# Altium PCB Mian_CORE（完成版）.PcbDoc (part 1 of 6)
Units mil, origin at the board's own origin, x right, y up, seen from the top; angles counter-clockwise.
Board outline 2755.91 x 1771.65 mil, 4 copper layers (TOP, GND02, PWR03, BOTTOM); 61 components, 130 nets, 4907 pads, 497 vias.
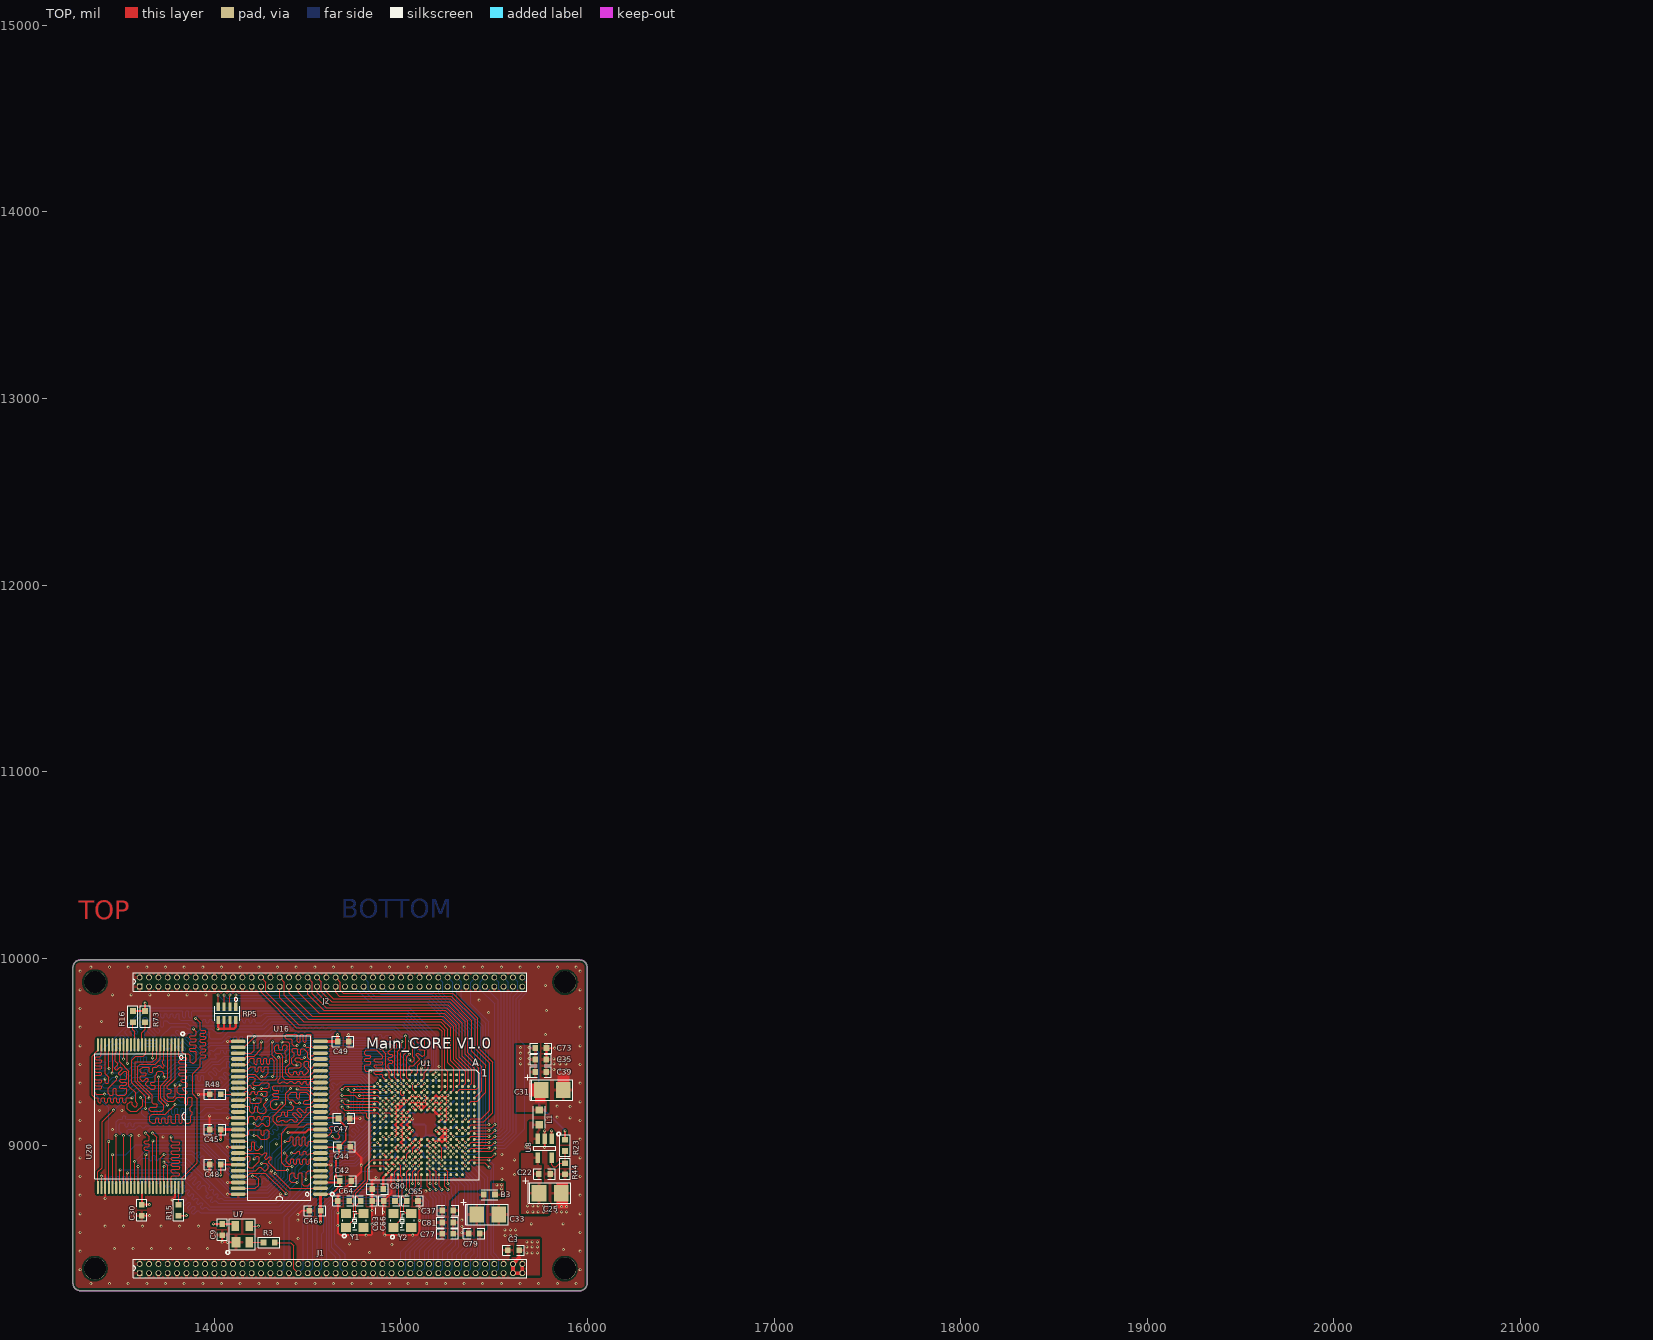
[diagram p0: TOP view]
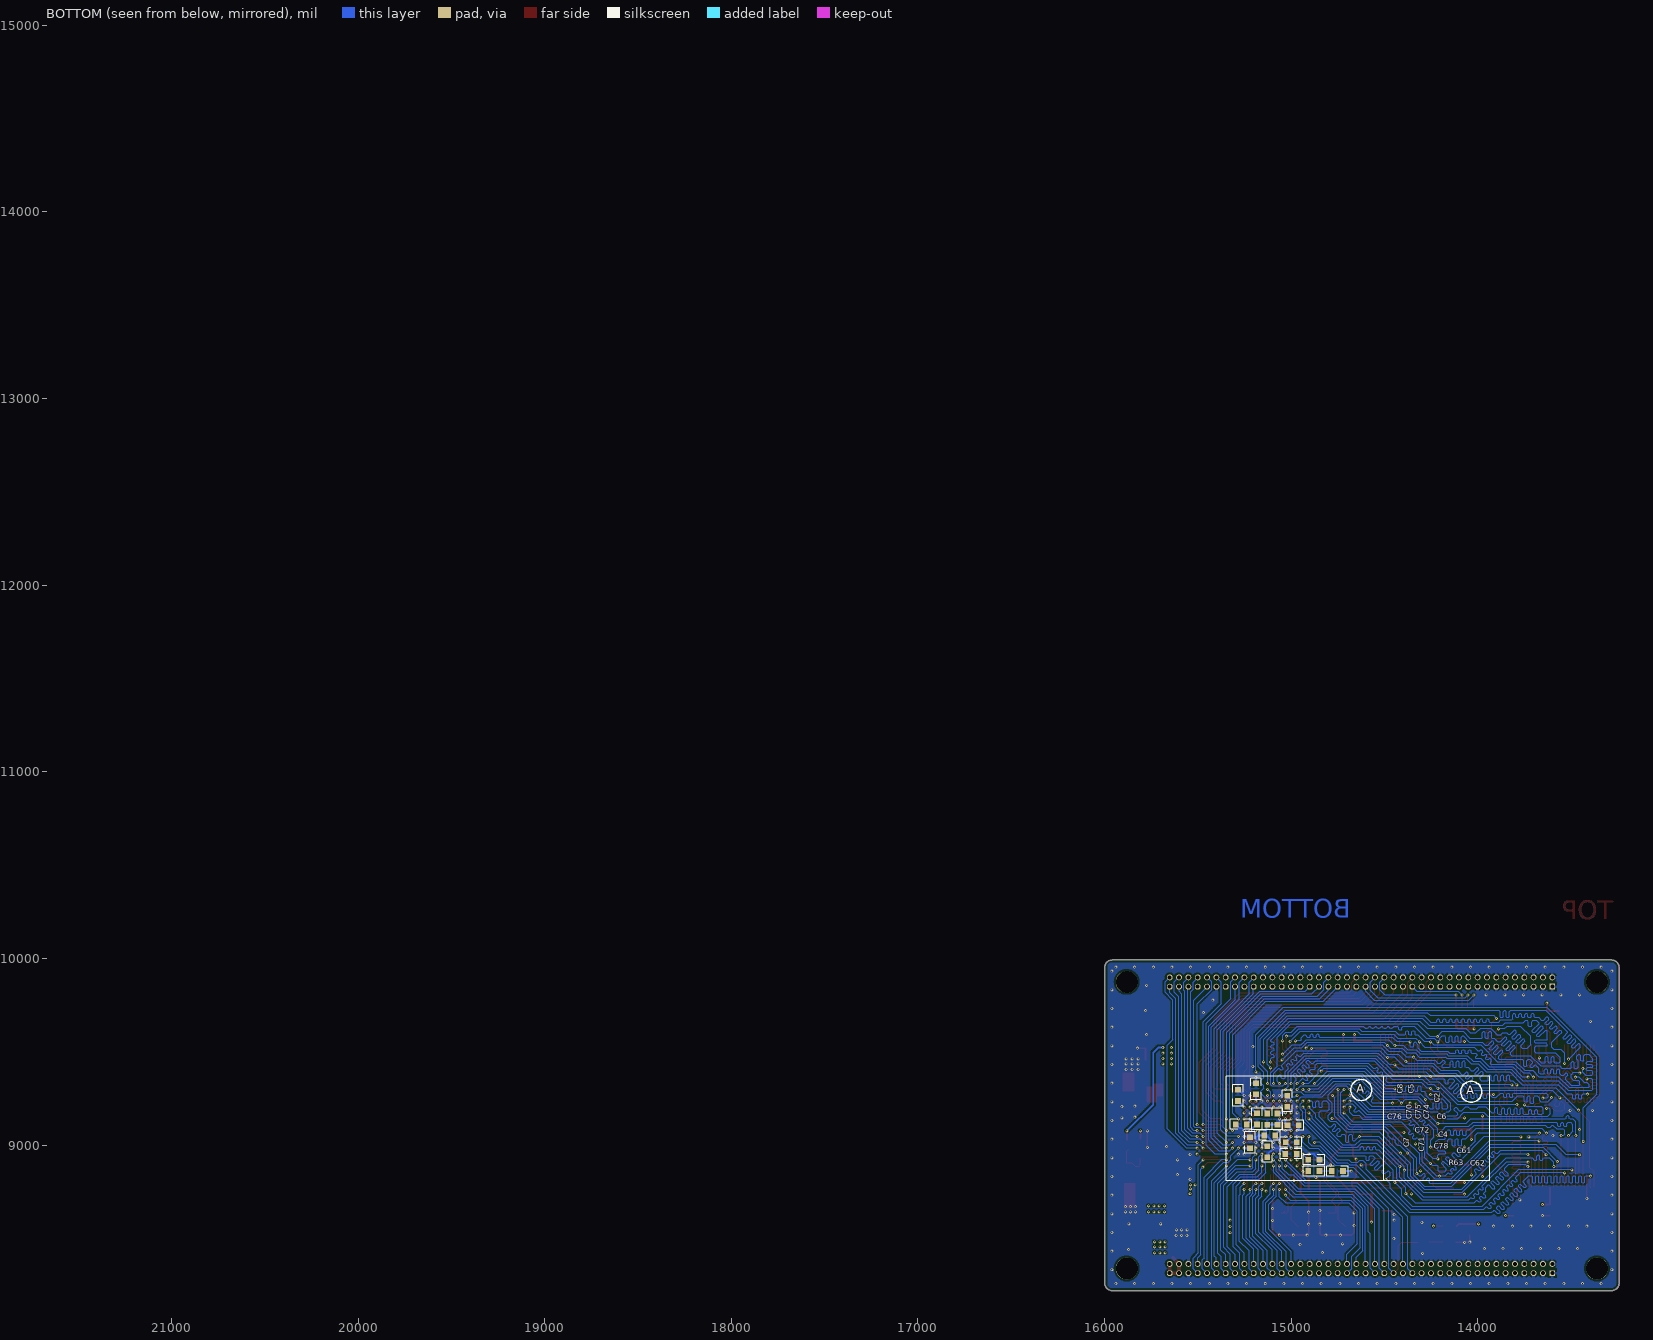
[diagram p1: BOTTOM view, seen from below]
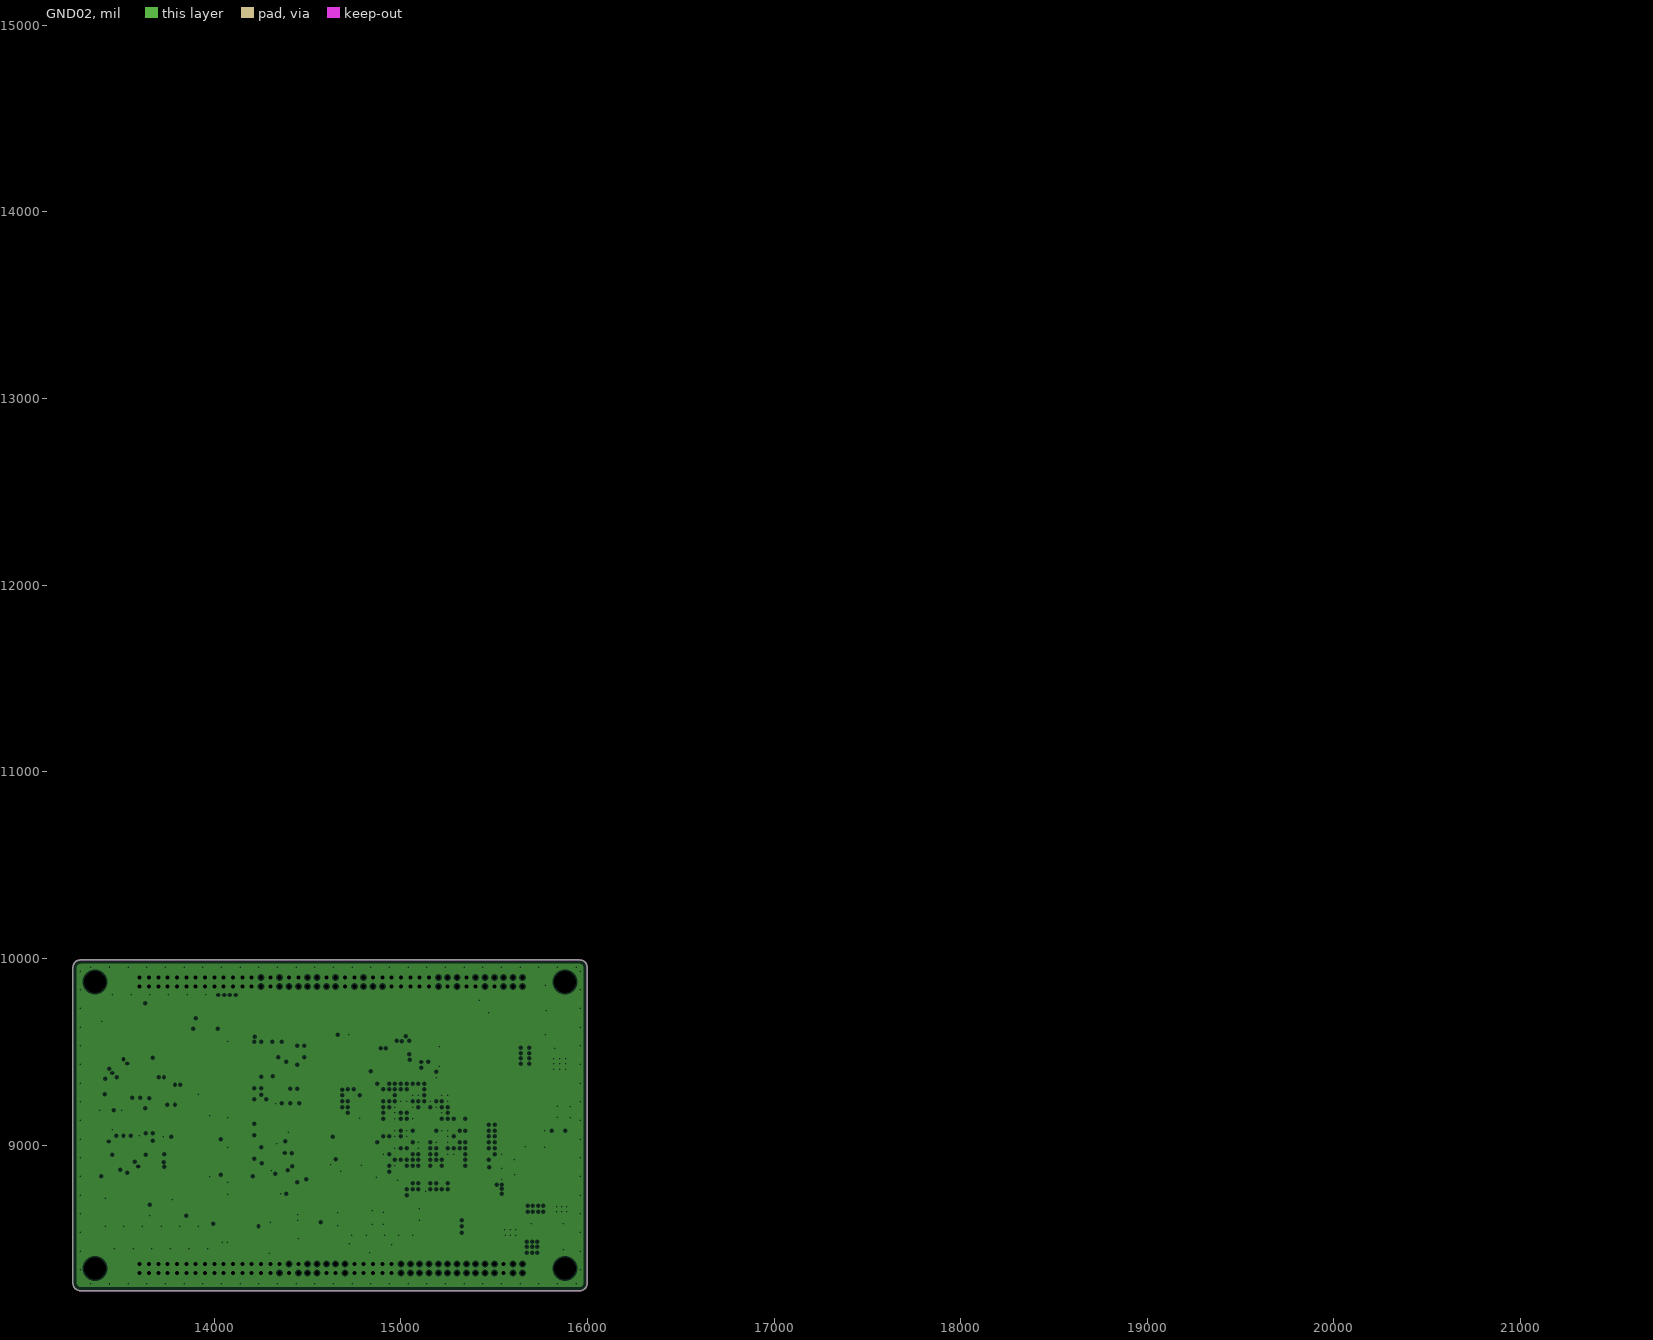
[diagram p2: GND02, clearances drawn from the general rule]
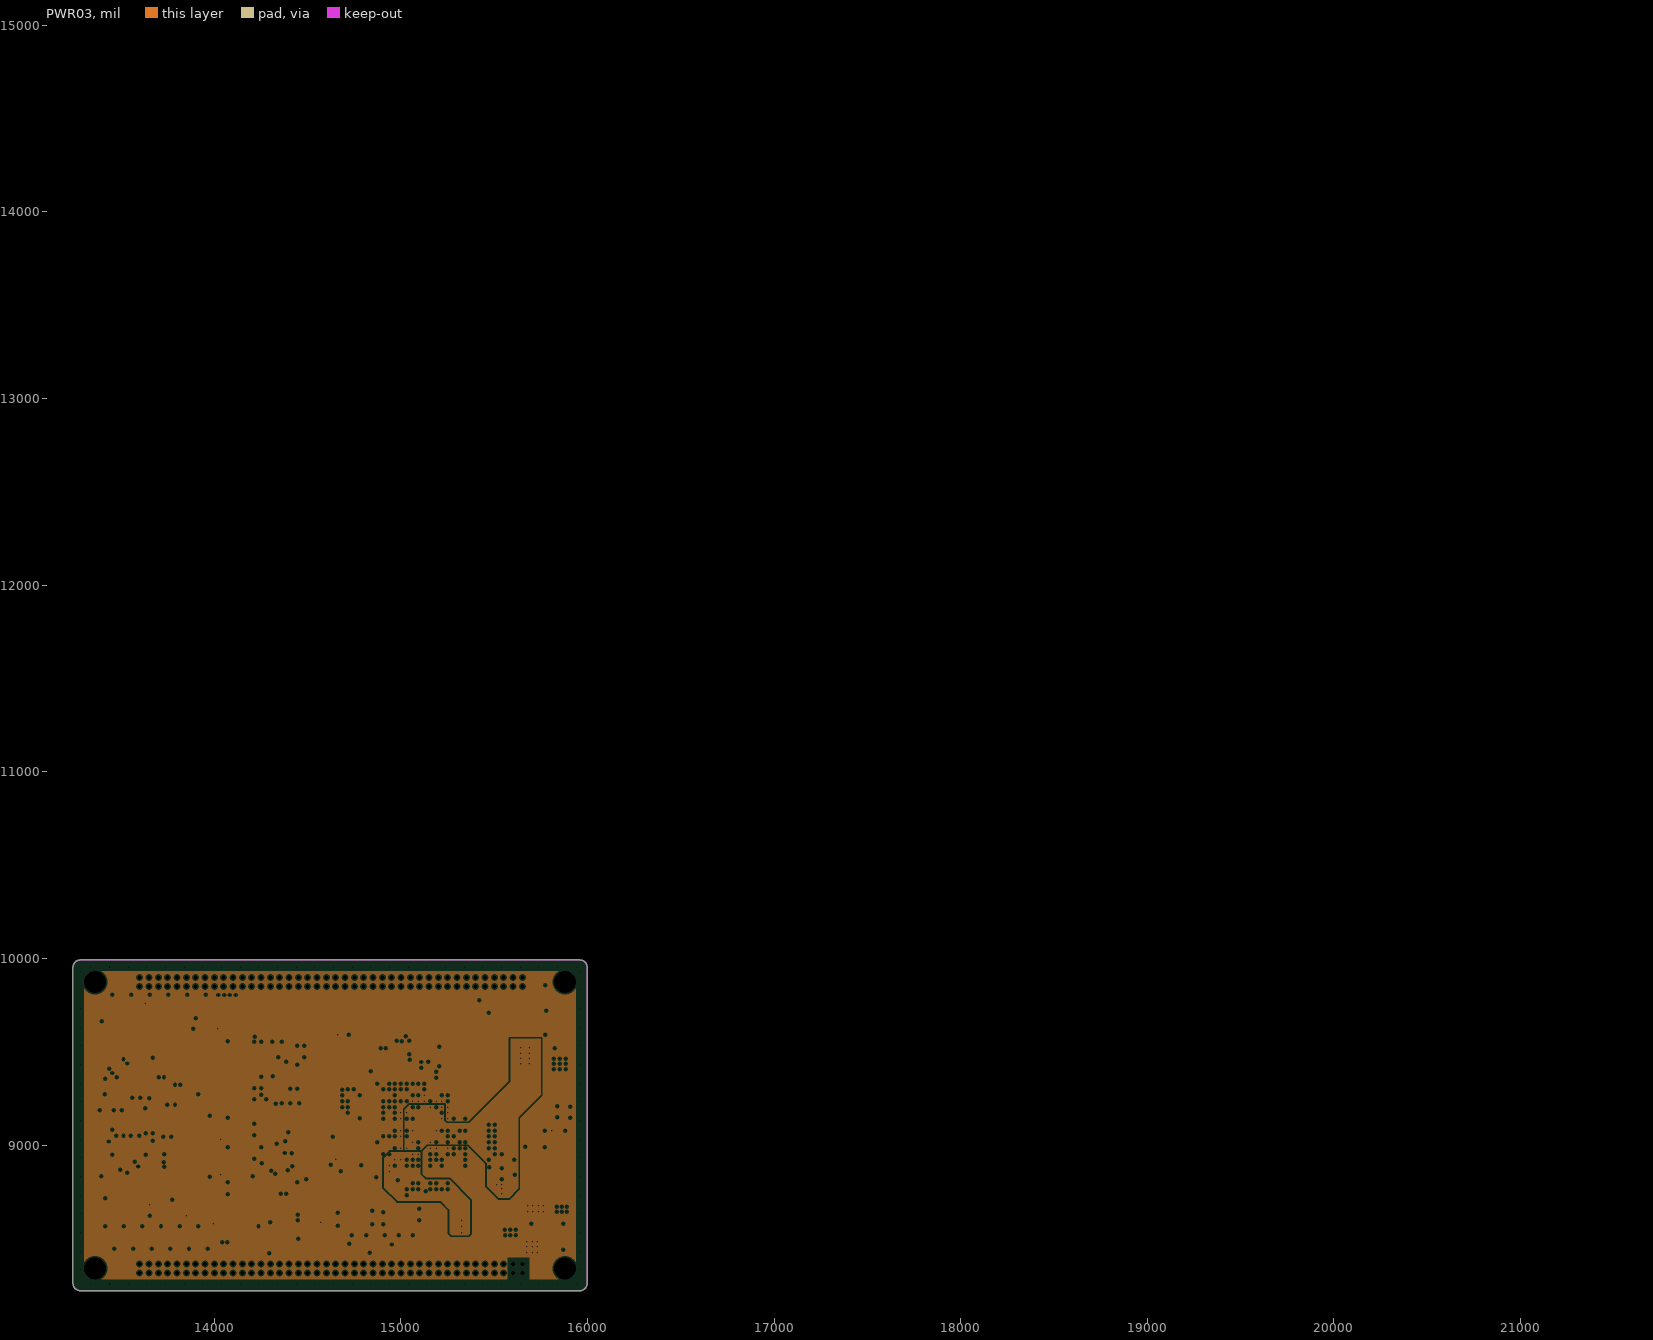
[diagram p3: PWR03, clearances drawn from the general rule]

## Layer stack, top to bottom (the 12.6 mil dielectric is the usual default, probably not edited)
TOP: signal copper 1.4
Dielectric: core 12.6, FR-4, Dk 4.8
GND02: plane copper 1.4, net GND
Dielectric: prepreg 12.6, FR-4, Dk 4.8
PWR03: plane copper 1.4, net (Multiple Nets)
Dielectric: core 12.6, FR-4, Dk 4.8
BOTTOM: signal copper 1.4

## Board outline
13243,8259.37 ccw(c13282.37,8259.37) 13282.37,8220 15959.54,8220 ccw(c15959.54,8259.37) 15998.91,8259.37 15998.91,9952.28 ccw(c15959.54,9952.28) 15959.54,9991.65 13282.37,9991.65 ccw(c13282.37,9952.28) 13243,9952.28

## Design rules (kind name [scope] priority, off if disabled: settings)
Clearance VIA-PLOY [(IsVia) vs INPOLY] p1: gap=5
Clearance POLY [(INPolygon)] p2: gap=10
Clearance ALL [All] p3: gap=4.5
PlaneClearance [All] p1: clearance=8
PlaneConnect [All] p1: planeconnectstyle=Relief reliefexpansion=6 reliefentries=4 reliefconductorwidth=10 reliefairgap=8
PolygonConnect PolygonConnect_via [isvia] p1: connectstyle=Direct reliefconductorwidth=10 reliefentries=4 polygonreliefangle="90 Angle"
PolygonConnect [All] p2: connectstyle=Relief reliefconductorwidth=15 reliefentries=4 polygonreliefangle="90 Angle"
RoutingVias [All] p1: holewidth=8 width=16 viastyle="Through Hole" minholewidth=8 minwidth=16 maxholewidth=8 maxwidth=16
SilkscreenOverComponentPads [All] p1: minsilkscreentomaskgap=10
SolderMaskExpansion [All] p1: expansion=2.5
Width PWR [InNetClass('PWR')] p1: maxlimit=60 minlimit=10 preferedwidth=12
Width [All] p2: maxlimit=5.5 minlimit=5.5 preferedwidth=5.5
25 further rules are at their usual default settings.

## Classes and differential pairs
net class ADD: A15 A16 A17 A18 A19 NCS0 NOE
net class adress: A0 A1 A2 A3 A4 A5 A6 A7 A8 A9 A10 A11 A12 A13 A14 LDQM0 LDQM1 LNSDCAS LNSDCS0 LNSDRAS NWE SDR_CKE0 SDR_CLK
net class D[0..31]: D0 D1 D2 D3 D4 D5 D6 D7 D8 D9 D10 D11 D12 D13 D14 D15
component class sdram: C42 C44 C45 C46 C47 C48 C49 R48 U16
component class EMC: U1
component class power: C2 C3 C4 C5 C6 C7 C8 C61 C62 C70 C71 C72 C73 C74 C75 C76 C77 C78 C79 C80 C81 R63
component class flash: C30 C63 C64 C65 C66 R15 R16 R73 U20 Y1 Y2
component class interface: B3 C9 C22 C25 C31 C33 C35 C37 C39 J1 J2 L1 R3 R23 R44 U7 U8
component class CPU: RP5
net class PWR: DP1V2 DP1V2_PLL DP3V3 GND
net class DZ: EXT_RST GPI_00 GPI_02 GPI_03 GPI_04 GPI_05 GPI_07 GPI_08 GPI_16 GPI_22 GPIO_00 GPIO_01 GPO_00 GPO_01 GPO_02 GPO_03 GPO_05 GPO_06 GPO_07 GPO_08 GPO_09 GPO_10 GPO_12 GPO_13 GPO_14 GPO_15 GPO_16 GPO_20 MISO0 MISO1 MOSI0 MOSI1 NCS1 NCS2 NRESET NSYSRESET NTRST P0.2 P0.3 P0.4 P0.5 P0.6 P0.7 RTCK SCK0 SCK1 SCL1 SCL2 SDA1 SDA2 SERVICES_N SSEL0 SSEL1 TCK TDI TDO TMS U1_RX U1_TX U2_RX U2_TX U3_RX U3_TX U4_TX U5_RX U5_TX U6_RX U6_TX

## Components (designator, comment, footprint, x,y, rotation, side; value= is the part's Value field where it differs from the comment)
B3 "" 0603 15475,8734 r180 top
C2 "104" 0603C 15021,9234.92 r90 bottom
C3 "104" 0603C 15604.08,8436 r180 top
C4 "104" 0603C 15000.08,9015 r180 bottom
C5 "104" 0603C 15188,9301.08 r90 bottom
C6 "104" 0603C 14990,9106 r180 bottom
C7 "104" 0603C 15220.49,9012.94 r90 bottom
C8 "104" 0603C 15285,9265.92 r90 bottom
C9 "104" 0603C 14043,8547.08 r270 top
C22 "104" 0603C 15769.92,8845 r180 top
C25 "22uF" TC-3528 15800.06,8742 r0 top
C30 "104" 0603C 13612,8651.08 r270 top
C31 "10uF" TC-3528 15811.06,9295 r0 top
C33 "10uF" TC-3528 15466,8627 r0 top
C35 "103" 0603C 15749.92,9458 r180 top
C37 "104" 0603C 15252,8649 r0 top
C39 "104" 0603C 15749.92,9392 r180 top
C42 "104" 0603C 14703.6,8807 r0 top
C44 "103" 0603C 14699,8991 r0 top
C45 "104" 0603C 14005,9083 r180 top
C46 "104" 0603C 14540.08,8648 r180 top
C47 "104" 0603C 14695.92,9143 r0 top
C48 "104" 0603C 14005,8896 r180 top
C49 "104" 0603C 14691,9555 r0 top
C61 "150pf 5%" 0603C 14878.08,8921 r180 bottom
C62 "3.9nf 5%" 0603C 14752.08,8860 r180 bottom
C63 "22pf" 0603C 14816.08,8701 r0 top
C64 "22pf" 0603C 14693.08,8701 r180 top
C65 "12pf" 0603C 15062.08,8701 r0 top
C66 "12pf" 0603C 14939.08,8701 r180 top
C70 "104" 0603C 15183,9140.08 r270 bottom
C71 "104" 0603C 15128,8964.08 r270 bottom
C72 "104" 0603C 15114.92,9052 r0 bottom
C73 "104" 0603C 15750.92,9519 r0 top
C74 "104" 0603C 15074,9139.08 r270 bottom
C75 "104" 0603C 15128,9139.08 r270 bottom
C76 "104" 0603C 15267.92,9111 r0 bottom
C77 "104" 0603C 15251.08,8524.5 r180 top
C78 "104" 0603C 15000.92,8953 r0 bottom
C79 "104" 0603C 15392.92,8526 r0 top
C80 "104" 0603C 14876.08,8764 r180 top
C81 "104" 0603C 15251.08,8585 r180 top
J1 "CONN PLUG 42 x 2" DIP84 13600.95,8313.11 r90 top
J2 "CONN PLUG 42 x 2" DIP84 13600.95,9848.54 r90 top
L1 "2.2UH" 0805 15742,9148.37 r90 top
R3 "470" 0603R 14293.92,8478 r0 top
R15 "10K" 0603R 13809,8651.08 r90 top
R16 "10K" 0603R 13564,9688.23 r270 top
R23 "100K 1%" 0603R 15880,8997.92 r270 top
R44 "100K 1%" 0603R 15880,8872.92 r270 top
R48 "10K" 0603R 14005,9272 r0 top
R63 "120K 1%" 0603R 14878.08,8860 r180 bottom
R73 "10K" 0603R 13630,9688.23 r270 top
RP5 "10K" PZ-4-0.8B 14068.76,9705.57 r180 top
U1 "LPC3250" TFBGA296 15126,9109 r270 top
U7 "MAX811" MAX811 14150.6,8522.31 r0 top
U8 "SP6669" SOT-23-5 15771,8983 r180 top
U16 "HY57V561620CLT" TSSOP-54 14349,9146 r90 top locked
U20 "SST36VF1601" TSOP-48 13603,9155 r180 top
Y1 "13M" XTAL-D 14753,8596 r0 top
Y2 "32.768K" XTAL-D 15007.94,8596 r0 top locked

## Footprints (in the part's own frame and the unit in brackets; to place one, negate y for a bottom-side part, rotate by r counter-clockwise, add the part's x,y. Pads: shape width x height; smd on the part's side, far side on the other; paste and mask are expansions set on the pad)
0603 [mm]
  rect 0.76x0.8 smd: 1(-0.76,0) 2(0.76,0)
  silkscreen extent -1.15,-0.7 1.15,0.7
0603C [mm]
  rect 0.76x0.8 smd: 1(-0.76,0) 2(0.76,0)
  silkscreen extent -1.46,-0.7 1.46,0.7
0603R [mm]
  rect 0.76x0.8 smd: 1(-0.76,0) 2(0.76,0)
  silkscreen extent -1.46,-0.7 1.46,0.7
0805 [mm]
  rect 1x1 smd: 1(-1,0) 2(1,0)
  silkscreen extent -1.5,-0.8 1.5,0.8
DIP84 [mm]
  rect 0.8x0.8 hole 0.55: 1(0,0)
  round 0.8 hole 0.55: 2(1.27,0) 3(0,-1.27) 4(1.27,-1.27) 5(0,-2.54) 6(1.27,-2.54) 7(0,-3.81) 8(1.27,-3.81) 9(0,-5.08) 10(1.27,-5.08) 11(0,-6.35) 12(1.27,-6.35) 13(0,-7.62) 14(1.27,-7.62) 15(0,-8.89) 16(1.27,-8.89) 17(0,-10.16) 18(1.27,-10.16) 19(0,-11.43) 20(1.27,-11.43) 21(0,-12.7) 22(1.27,-12.7) 23(0,-13.97) 24(1.27,-13.97) 25(0,-15.24) 26(1.27,-15.24) 27(0,-16.51) 28(1.27,-16.51) 29(0,-17.78) 30(1.27,-17.78) 31(0,-19.05) 32(1.27,-19.05) 33(0,-20.32) 34(1.27,-20.32) 35(0,-21.59) 36(1.27,-21.59) 37(0,-22.86) 38(1.27,-22.86) 39(0,-24.13) 40(1.27,-24.13) 41(0,-25.4) 42(1.27,-25.4) 43(0,-26.67) 44(1.27,-26.67) 45(0,-27.94) 46(1.27,-27.94) 47(0,-29.21) 48(1.27,-29.21) 49(0,-30.48) 50(1.27,-30.48) 51(0,-31.75) 52(1.27,-31.75) 53(0,-33.02) 54(1.27,-33.02) 55(0,-34.29) 56(1.27,-34.29) 57(0,-35.56) 58(1.27,-35.56) 59(0,-36.83) 60(1.27,-36.83) 61(0,-38.1) 62(1.27,-38.1) 63(0,-39.37) 64(1.27,-39.37) 65(0,-40.64) 66(1.27,-40.64) 67(0,-41.91) 68(1.27,-41.91) 69(0,-43.18) 70(1.27,-43.18) 71(0,-44.45) 72(1.27,-44.45) 73(0,-45.72) 74(1.27,-45.72) 75(0,-46.99) 76(1.27,-46.99) 77(0,-48.26) 78(1.27,-48.26) 79(0,-49.53) 80(1.27,-49.53) 81(0,-50.8) 82(1.27,-50.8) 83(0,-52.07) 84(1.27,-52.07)
  silkscreen extent -0.64,-52.71 1.91,0.89
MAX811 [mm]
  rect 1.2x1.4 smd: 1(-0.85,-1.1)
  rect 1x1.4 smd: 2(0.95,-1.1) 3(0.95,1.1) 4(-0.95,1.1)
  silkscreen extent -2.23,-2.74 1.75,2.1
PZ-4-0.8B [mm]
  rect 0.5x1.1 smd: 1(-1.2,-0.9) 4(1.2,-0.9) 5(1.2,0.9) 8(-1.2,0.9)
  rect 0.4x1.1 smd: 2(-0.4,-0.9) 3(0.4,-0.9) 6(0.4,0.9) 7(-0.4,0.9)
  silkscreen extent -1.7,-2.15 1.7,1
SOT-23-5 [mm]
  rect 0.6x1.4 smd: 1(-0.95,-1.3) 2(0,-1.3) 3(0.95,-1.3) 4(0.95,1.3) 5(-0.95,1.3)
  silkscreen extent -2.15,-2.18 1.5,0.3
TC-3528 [mm]
  rect 2x2.2 smd: 1(-1.5,0) 2(1.5,0)
  silkscreen extent -3.7,-1.4 2.8,2.1
TFBGA296 [mm]
  round 0.4 smd: A3(-5.2,6.8) A4(-4.4,6.8) A5(-3.6,6.8) A6(-2.8,6.8) A7(-2,6.8) A8(-1.2,6.8) A9(-0.4,6.8) A10(0.4,6.8) A11(1.2,6.8) A12(2,6.8) A13(2.8,6.8) A14(3.6,6.8) A15(4.4,6.8) A16(5.2,6.8) B2(-6,6) B3(-5.2,6) B4(-4.4,6) B5(-3.6,6) B6(-2.8,6) B7(-2,6) B8(-1.2,6) B9(-0.4,6) B10(0.4,6) B11(1.2,6) B12(2,6) B13(2.8,6) B14(3.6,6) B15(4.4,6) B16(5.2,6) B17(6,6) C1(-6.8,5.2) C2(-6,5.2) C3(-5.2,5.2) C4(-4.4,5.2) C5(-3.6,5.2) C6(-2.8,5.2) C7(-2,5.2) C8(-1.2,5.2) C9(-0.4,5.2) C10(0.4,5.2) C11(1.2,5.2) C12(2,5.2) C13(2.8,5.2) C14(3.6,5.2) C15(4.4,5.2) C16(5.2,5.2) C17(6,5.2) C18(6.8,5.2) D1(-6.8,4.4) D2(-6,4.4) D3(-5.2,4.4) D4(-4.4,4.4) D5(-3.6,4.4) D6(-2.8,4.4) D7(-2,4.4) D8(-1.2,4.4) D9(-0.4,4.4) D10(0.4,4.4) D11(1.2,4.4) D12(2,4.4) D13(2.8,4.4) D14(3.6,4.4) D15(4.4,4.4) D16(5.2,4.4) D17(6,4.4) D18(6.8,4.4) E1(-6.8,3.6) E2(-6,3.6) E3(-5.2,3.6) E4(-4.4,3.6) E5(-3.6,3.6) E6(-2.8,3.6) E7(-2,3.6) E8(-1.2,3.6) E9(-0.4,3.6) E10(0.4,3.6) E11(1.2,3.6) E12(2,3.6) E13(2.8,3.6) E14(3.6,3.6) E15(4.4,3.6) E16(5.2,3.6) E17(6,3.6) E18(6.8,3.6) F1(-6.8,2.8) F2(-6,2.8) F3(-5.2,2.8) F4(-4.4,2.8) F5(-3.6,2.8) F6(-2.8,2.8) F7(-2,2.8) F8(-1.2,2.8) F9(-0.4,2.8) F10(0.4,2.8) F11(1.2,2.8) F12(2,2.8) F13(2.8,2.8) F14(3.6,2.8) F15(4.4,2.8) F16(5.2,2.8) F17(6,2.8) F18(6.8,2.8) G1(-6.8,2) G2(-6,2) G3(-5.2,2) G4(-4.4,2) G5(-3.6,2) G6(-2.8,2) G7(-2,2) G8(-1.2,2) G9(-0.4,2) G10(0.4,2) G11(1.2,2) G12(2,2) G13(2.8,2) G14(3.6,2) G15(4.4,2) G16(5.2,2) G17(6,2) G18(6.8,2) H1(-6.8,1.2) H2(-6,1.2) H3(-5.2,1.2) H4(-4.4,1.2) H5(-3.6,1.2) H6(-2.8,1.2) H7(-2,1.2) H12(2,1.2) H13(2.8,1.2) H14(3.6,1.2) H15(4.4,1.2) H16(5.2,1.2) H17(6,1.2) H18(6.8,1.2) J1(-6.8,0.4) J2(-6,0.4) J3(-5.2,0.4) J4(-4.4,0.4) J5(-3.6,0.4) J6(-2.8,0.4) J7(-2,0.4) J12(2,0.4) J13(2.8,0.4) J14(3.6,0.4) J15(4.4,0.4) J16(5.2,0.4) J17(6,0.4) J18(6.8,0.4) K1(-6.8,-0.4) K2(-6,-0.4) K3(-5.2,-0.4) K4(-4.4,-0.4) K5(-3.6,-0.4) K6(-2.8,-0.4) K7(-2,-0.4) K12(2,-0.4) K13(2.8,-0.4) K14(3.6,-0.4) K15(4.4,-0.4) K16(5.2,-0.4) K17(6,-0.4) K18(6.8,-0.4) L1(-6.8,-1.2) L2(-6,-1.2) L3(-5.2,-1.2) L4(-4.4,-1.2) L5(-3.6,-1.2) L6(-2.8,-1.2) L7(-2,-1.2) L12(2,-1.2) L13(2.8,-1.2) L14(3.6,-1.2) L15(4.4,-1.2) L16(5.2,-1.2) L17(6,-1.2) L18(6.8,-1.2) M1(-6.8,-2) M2(-6,-2) M3(-5.2,-2) M4(-4.4,-2) M5(-3.6,-2) M6(-2.8,-2) M7(-2,-2) M8(-1.2,-2) M9(-0.4,-2) M10(0.4,-2) M11(1.2,-2) M12(2,-2) M13(2.8,-2) M14(3.6,-2) M15(4.4,-2) M16(5.2,-2) M17(6,-2) M18(6.8,-2) N1(-6.8,-2.8) N2(-6,-2.8) N3(-5.2,-2.8) N4(-4.4,-2.8) N5(-3.6,-2.8) N6(-2.8,-2.8) N7(-2,-2.8) N8(-1.2,-2.8) N9(-0.4,-2.8) N10(0.4,-2.8) N11(1.2,-2.8) N12(2,-2.8) N13(2.8,-2.8) N14(3.6,-2.8) N15(4.4,-2.8) N16(5.2,-2.8) N17(6,-2.8) N18(6.8,-2.8) P1(-6.8,-3.6) P2(-6,-3.6) P3(-5.2,-3.6) P4(-4.4,-3.6) P5(-3.6,-3.6) P6(-2.8,-3.6) P7(-2,-3.6) P8(-1.2,-3.6) P9(-0.4,-3.6) P10(0.4,-3.6) P11(1.2,-3.6) P12(2,-3.6) P13(2.8,-3.6) P14(3.6,-3.6) P15(4.4,-3.6) P16(5.2,-3.6) P17(6,-3.6) P18(6.8,-3.6) R1(-6.8,-4.4) R2(-6,-4.4) R3(-5.2,-4.4) R4(-4.4,-4.4) R5(-3.6,-4.4) R6(-2.8,-4.4) R7(-2,-4.4) R8(-1.2,-4.4) R9(-0.4,-4.4) R10(0.4,-4.4) R11(1.2,-4.4) R12(2,-4.4) R13(2.8,-4.4) R14(3.6,-4.4) R15(4.4,-4.4) R16(5.2,-4.4) R17(6,-4.4) R18(6.8,-4.4) T1(-6.8,-5.2) T2(-6,-5.2) T3(-5.2,-5.2) T4(-4.4,-5.2) T5(-3.6,-5.2) T6(-2.8,-5.2) T7(-2,-5.2) T8(-1.2,-5.2) T9(-0.4,-5.2) T10(0.4,-5.2) T11(1.2,-5.2) T12(2,-5.2) T13(2.8,-5.2) T14(3.6,-5.2) T15(4.4,-5.2) T16(5.2,-5.2) T17(6,-5.2) T18(6.8,-5.2) U2(-6,-6) U3(-5.2,-6) U4(-4.4,-6) U5(-3.6,-6) U6(-2.8,-6) U7(-2,-6) U8(-1.2,-6) U9(-0.4,-6) U10(0.4,-6) U11(1.2,-6) U12(2,-6) U13(2.8,-6) U14(3.6,-6) U15(4.4,-6) U16(5.2,-6) U17(6,-6) V3(-5.2,-6.8) V4(-4.4,-6.8) V5(-3.6,-6.8) V6(-2.8,-6.8) V7(-2,-6.8) V8(-1.2,-6.8) V9(-0.4,-6.8) V10(0.4,-6.8) V11(1.2,-6.8) V12(2,-6.8) V13(2.8,-6.8) V14(3.6,-6.8) V15(4.4,-6.8) V16(5.2,-6.8)
  silkscreen extent -7.5,-7.5 7.5,7.5
TSOP-48 [mm]
  oval 0.28x1.8 smd: 1(-5.75,-9.7) 2(-5.25,-9.7) 3(-4.75,-9.7) 4(-4.25,-9.7) 5(-3.75,-9.7) 6(-3.25,-9.7) 7(-2.75,-9.7) 8(-2.25,-9.7) 9(-1.75,-9.7) 10(-1.25,-9.7) 11(-0.75,-9.7) 12(-0.25,-9.7) 13(0.25,-9.7) 14(0.75,-9.7) 15(1.25,-9.7) 16(1.75,-9.7) 17(2.25,-9.7) 18(2.75,-9.7) 19(3.25,-9.7) 20(3.75,-9.7) 21(4.25,-9.7) 22(4.75,-9.7) 23(5.25,-9.7) 24(5.75,-9.7) 25(5.75,9.7) 26(5.25,9.7) 27(4.75,9.7) 28(4.25,9.7) 29(3.75,9.7) 30(3.25,9.7) 31(2.75,9.7) 32(2.25,9.7) 33(1.75,9.7) 34(1.25,9.7) 35(0.75,9.7) 36(0.25,9.7) 37(-0.25,9.7) 38(-0.75,9.7) 39(-1.25,9.7) 40(-1.75,9.7) 41(-2.25,9.7) 42(-2.75,9.7) 43(-3.25,9.7) 44(-3.75,9.7) 45(-4.25,9.7) 46(-4.75,9.7) 47(-5.25,9.7) 48(-5.75,9.7)
  silkscreen extent -6.2,-11.45 6.2,8.5
TSSOP-54 [mm]
  oval 0.5x2 smd: 1(-10.4,-5.6) 2(-9.6,-5.6) 3(-8.8,-5.6) 4(-8,-5.6) 5(-7.2,-5.6) 6(-6.4,-5.6) 7(-5.6,-5.6) 8(-4.8,-5.6) 9(-4,-5.6) 10(-3.2,-5.6) 11(-2.4,-5.6) 12(-1.6,-5.6) 13(-0.8,-5.6) 14(0,-5.6) 15(0.8,-5.6) 16(1.6,-5.6) 17(2.4,-5.6) 18(3.2,-5.6) 19(4,-5.6) 20(4.8,-5.6) 21(5.6,-5.6) 22(6.4,-5.6) 23(7.2,-5.6) 24(8,-5.6) 25(8.8,-5.6) 26(9.6,-5.6) 27(10.4,-5.6) 28(10.4,5.6) 29(9.6,5.6) 30(8.8,5.6) 31(8,5.6) 32(7.2,5.6) 33(6.4,5.6) 34(5.6,5.6) 35(4.8,5.6) 36(4,5.6) 37(3.2,5.6) 38(2.4,5.6) 39(1.6,5.6) 40(0.8,5.6) 41(0,5.6) 42(-0.8,5.6) 43(-1.6,5.6) 44(-2.4,5.6) 45(-3.2,5.6) 46(-4,5.6) 47(-4.8,5.6) 48(-5.6,5.6) 49(-6.4,5.6) 50(-7.2,5.6) 51(-8,5.6) 52(-8.8,5.6) 53(-9.6,5.6) 54(-10.4,5.6)
  silkscreen extent -11.2,-7.45 11.2,4.3
XTAL-D [mm]
  rect 1.4x1.2 smd: 1(-1.2,-0.95) 2(1.2,0.95) 3(1.2,-0.95) 4(-1.2,0.95)
  silkscreen extent -1.67,-2.36 1.6,1.25

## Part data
B3 L1: library part INDUCTOR
C2 C3 C4 C5 C6 C7 C8 C9 C22 C30 C35 C37 C39 C42 C44 C45 C46 C47 C48 C49 C61 C62 C63 C64 C65 C66 C70 C71 C72 C73 C74 C75 C76 C77 C78 C79 C80 C81: library part CAP, "Capacitor"
C25 C31 C33: library part CAPACITOR, "Capacitor"
R3: library part RES1
R15 R16 R23 R44 R48 R63 R73: library part RES
RP5: library part RP4
U1: library part LPC3250A
U8: library part SP6659
Y1 Y2: library part CRYSTAL, "Crystal"

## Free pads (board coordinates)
  round 118.11 hole 118.11 unplated: 0(13361.11,8338.11) 0(13361.11,9873.54) 0(15880.8,8338.11) 0(15880.8,9873.54)
  round 5.12 on Drill Drawing: 1(17273.63,9762.51) 1(17274.63,9738.97) 1(17275.62,8308.02) 1(17275.62,8308.02) 1(17275.62,11284.8) 1(17275.62,11338.3) 1(17275.62,12656.02) 1(17275.62,12803.26) 1(17275.62,12959.96) 1(17275.62,13019.88) 1(17275.62,13019.88) 1(17275.62,13109.96) 1(17275.62,13259.96) 1(17275.62,13409.96) 1(17275.62,13559.96) 1(17275.62,13709.96) 1(17275.62,13860.36) 1(17275.62,13910.36) 1(17275.62,14060.36) 1(17275.62,14210.36) 1(17275.62,14360.36) 1(17275.62,14660.36) 1(17275.62,14710.36) 1(17275.62,14860.36) 1(17275.62,14860.36) 1(17400.46,12556.37) 1(17400.46,12556.37) 1(17400.46,12561.03) 1(17400.46,12561.03) 1(17401.46,12551.7) 1(17401.46,12551.7) 1(17401.46,12565.7) 1(17401.46,12565.7) 1(17403.46,12547.62) 1(17403.46,12547.62) 1(17403.46,12569.78) 1(17403.46,12569.78) 1(17406.46,12544.12) 1(17406.46,12544.12) 1(17406.46,12573.28) 1(17406.46,12573.28) 1(17409.96,12541.78) 1(17409.96,12541.78) 1(17409.96,12575.62) 1(17409.96,12575.62) 1(17413.96,12541.2) 1(17413.96,12541.2) 1(17413.96,12576.2) 1(17413.96,12576.2) 1(17417.96,12541.78) 1(17417.96,12541.78) 1(17417.96,12575.62) 1(17417.96,12575.62) 1(17421.46,12544.12) 1(17421.46,12544.12) 1(17421.46,12573.28) 1(17421.46,12573.28) 1(17424.46,12547.62) 1(17424.46,12547.62) 1(17424.46,12569.78) 1(17424.46,12569.78) 1(17426.46,12551.7) 1(17426.46,12551.7) 1(17426.46,12565.7) 1(17426.46,12565.7) 1(17427.46,12556.37) 1(17427.46,12556.37) 1(17427.46,12561.03) 1(17427.46,12561.03) 1(17436.96,12564.53) 1(17443.96,12541.2) 1(17443.96,12576.2) 1(17450.96,12564.53) 1(17465.46,12541.2) 1(17465.46,12559.28) 1(17465.46,12576.2) 1(17467.96,12562.2) 1(17467.96,12562.2) 1(17470.46,12563.95) 1(17470.46,12563.95) 1(17474.46,12564.53) 1(17474.46,12564.53) 1(17477.46,12563.95) 1(17477.46,12563.95) 1(17480.96,12561.62) 1(17480.96,12561.62) 1(17482.46,12541.2) 1(17482.46,12558.12) 1(17482.46,12558.12) 1(17495.46,12551.12) 1(17495.46,12551.12) 1(17495.46,12554.62) 1(17495.46,12554.62) 1(17496.46,12547.62) 1(17496.46,12547.62) 1(17496.46,12556.95) 1(17496.46,12558.12) 1(17496.46,12558.12) 1(17498.46,12562.2) 1(17498.46,12562.2) 1(17498.96,12544.12) 1(17498.96,12544.12) 1(17501.46,12563.95) 1(17501.46,12563.95) 1(17501.96,12541.78) 1(17501.96,12541.78) 1(17504.96,12564.53) 1(17504.96,12564.53) 1(17505.46,12541.2) 1(17505.46,12541.2) 1(17508.46,12563.37) 1(17508.46,12563.37) 1(17508.96,12542.37) 1(17508.96,12542.37) 1(17510.96,12561.03) 1(17510.96,12561.03) 1(17512.46,12545.87) 1(17512.46,12556.95) 1(17512.46,12556.95) 1(17526.96,12541.2) 1(17526.96,12559.87) 1(17526.96,12564.53) 1(17529.46,12562.2) 1(17529.46,12562.2) 1(17531.96,12563.95) 1(17531.96,12563.95) 1(17535.46,12564.53) 1(17535.46,12564.53) 1(17537.96,12563.95) 1(17537.96,12563.95) 1(17540.96,12562.2) 1(17582.46,12541.2) 1(17582.46,12576.2) 1(17582.46,12576.2) 1(17605.46,12541.2) 1(17605.46,12541.2) 1(17605.46,12576.2) 1(17614.96,12552.87) 1(17614.96,12552.87) 1(17615.96,12548.2) 1(17615.96,12548.2) 1(17615.96,12557.53) 1(17615.96,12557.53) 1(17617.96,12544.12) 1(17617.96,12544.12) 1(17617.96,12561.62) 1(17617.96,12561.62) 1(17620.96,12541.78) 1(17620.96,12541.78) 1(17620.96,12563.95) 1(17620.96,12563.95) 1(17623.96,12541.2) 1(17623.96,12541.2) 1(17623.96,12564.53) 1(17623.96,12564.53) 1(17626.96,12541.78) 1(17626.96,12541.78) 1(17626.96,12563.95) 1(17626.96,12563.95) 1(17629.96,12544.12) 1(17629.96,12544.12) 1(17629.96,12561.62) 1(17629.96,12561.62) 1(17631.96,12548.2) 1(17631.96,12548.2) 1(17631.96,12557.53) 1(17631.96,12557.53) 1(17632.46,12552.87) 1(17632.46,12552.87) 1(17646.96,12564.53) 1(17653.96,12541.2) 1(17653.96,12576.2) 1(17660.96,12564.53) 1(17675.46,12551.12) 1(17675.46,12551.12) 1(17675.46,12554.62) 1(17675.46,12554.62) 1(17676.46,12547.62) 1(17676.46,12547.62) 1(17676.46,12556.95) 1(17676.46,12558.12) 1(17676.46,12558.12) 1(17678.46,12562.2) 1(17678.46,12562.2) 1(17678.96,12544.12) 1(17678.96,12544.12) 1(17681.46,12563.95) 1(17681.46,12563.95) 1(17681.96,12541.78) 1(17681.96,12541.78) 1(17684.96,12564.53) 1(17684.96,12564.53) 1(17685.46,12541.2) 1(17685.46,12541.2) 1(17686.02,8538.49) 1(17686.02,8538.49) 1(17686.02,8538.49) 1(17686.02,8648.33) 1(17686.02,8648.33) 1(17686.02,8758.18) 1(17686.02,8758.18) 1(17686.02,8868.02) 1(17686.02,8868.02) 1(17686.02,8868.02) 1(17686.02,8868.02) 1(17686.02,8868.02) 1(17686.18,9079.52) 1(17686.18,9079.52) 1(17686.18,9189.36) 1(17686.18,9299.2) 1(17686.18,9409.05) 1(17686.18,9518.89) 1(17686.18,9518.89) 1(17686.18,9518.89) 1(17688.46,12563.37) 1(17688.46,12563.37) 1(17688.96,12542.37) 1(17688.96,12542.37) 1(17690.96,12561.03) 1(17690.96,12561.03) 1(17692.46,12545.87) 1(17692.46,12556.95) 1(17692.46,12556.95) 1(17706.46,12545.28) 1(17707.96,12559.28) 1(17707.96,12559.28) 1(17708.96,12542.95) 1(17708.96,12542.95) 1(17708.96,12562.2) 1(17708.96,12562.2) 1(17709.96,12555.2) 1(17709.96,12555.2) 1(17710.96,12563.95) 1(17710.96,12563.95) 1(17712.46,12541.2) 1(17712.46,12541.2) 1(17713.96,12564.53) 1(17713.96,12564.53) 1(17715.46,12541.2) 1(17715.46,12541.2) 1(17716.96,12563.95) 1(17716.96,12563.95) 1(17718.46,12542.37) 1(17718.46,12542.37) 1(17718.96,12551.7) 1(17718.96,12551.7) 1(17719.96,12562.2) 1(17720.46,12544.12) 1(17720.46,12544.12) 1(17720.96,12549.95) 1(17720.96,12549.95) 1(17721.46,12546.45) 1(17721.46,12546.45) 1(17742.96,12540.62) 1(17742.96,12540.62) 1(17742.96,12541.78) 1(17742.96,12541.78) 1(17742.96,12556.37) 1(17742.96,12556.37) 1(17742.96,12557.53) 1(17742.96,12557.53) 1(17743.96,12540.03) 1(17743.96,12540.03) 1(17743.96,12542.37) 1(17743.96,12542.37) 1(17743.96,12555.78) 1(17743.96,12555.78) 1(17743.96,12558.12) 1(17743.96,12558.12) 1(17744.96,12540.62) 1(17744.96,12540.62) 1(17744.96,12541.78) 1(17744.96,12541.78) 1(17744.96,12556.37) 1(17744.96,12556.37) 1(17744.96,12557.53) 1(17744.96,12557.53) 1(18125.62,12959.96) 1(18125.62,13109.96) 1(18125.62,13109.96) 1(18125.62,13259.96) 1(18125.62,13259.96) 1(18125.62,13409.96) 1(18125.62,13409.96) 1(18125.62,13559.96) 1(18125.62,13559.96) 1(18125.62,13857.99) 1(18125.62,13910.36) 1(18125.62,14060.36) 1(18125.62,14060.36) 1(18125.62,14210.36) 1(18125.62,14210.36) 1(18125.62,14360.36) 1(18125.62,14360.36) 1(18125.62,14510.36) 1(18125.62,14510.36) 1(18125.62,14510.36) 1(18125.62,14660.36) 1(18125.62,14710.66) 1(18125.62,14860.36) 1(18136.02,8538.49) 1(18136.02,8868.02) 1(18136.18,9079.52) 1(18136.18,9518.89) 1(18136.18,9518.89) 1(18136.18,9518.89) 1(18172.38,14536.55) 1(18172.38,14536.55) 1(18172.38,14636.55) 1(18172.38,14636.55) 1(18174.83,13432.52) 1(18174.83,13432.52) 1(18174.83,13532.52) 1(18174.83,13532.52) 1(18175.62,12985.16) 1(18175.62,12985.16) 1(18175.62,12985.16) 1(18175.62,12985.16) 1(18175.62,13085.16) 1(18175.62,13085.16) 1(18175.62,13085.16) 1(18175.62,13085.16) 1(18175.62,13135.16) 1(18175.62,13135.16) 1(18175.62,13235.16) 1(18175.62,13235.16) 1(18175.62,13285.16) 1(18175.62,13285.16) 1(18175.62,13385.16) 1(18175.62,13385.16) 1(18175.62,13435.16) 1(18175.62,13435.16) 1(18175.62,13435.16) 1(18175.62,13435.16) 1(18175.62,13535.16) 1(18175.62,13535.16) 1(18175.62,13535.16) 1(18175.62,13535.16) 1(18175.62,13585.16) 1(18175.62,13585.16) 1(18175.62,13585.16) 1(18175.62,13585.16) 1(18175.62,13685.16) 1(18175.62,13685.16) 1(18175.62,13685.16) 1(18175.62,13685.16) 1(18175.62,13935.16) 1(18175.62,13935.16) 1(18175.62,13935.16) 1(18175.62,13935.16) 1(18175.62,14035.16) 1(18175.62,14035.16) 1(18175.62,14035.16) 1(18175.62,14035.16) 1(18175.62,14085.16) 1(18175.62,14085.16) 1(18175.62,14085.16) 1(18175.62,14085.16) 1(18175.62,14185.16) 1(18175.62,14185.16) 1(18175.62,14185.16) 1(18175.62,14185.16) 1(18175.62,14235.16) 1(18175.62,14235.16) 1(18175.62,14335.16) 1(18175.62,14335.16) 1(18175.62,14385.16) 1(18175.62,14385.16) 1(18175.62,14485.16) 1(18175.62,14485.16) 1(18180.73,13442.54) 1(18180.73,13446.66) 1(18180.73,13450.78) 1(18180.73,13454.9) 1(18180.73,13459.02) 1(18180.73,13463.14) 1(18180.73,13467.26) 1(18180.73,13471.38) 1(18180.73,13475.5) 1(18180.73,13479.62) 1(18180.73,13483.74) 1(18180.73,13487.86) 1(18180.73,13491.98) 1(18180.73,13496.1) 1(18180.73,13500.22) 1(18180.73,13504.34) 1(18180.73,13508.46) 1(18180.73,13512.58) 1(18180.73,13516.7) 1(18180.73,13520.82) 1(18180.73,13524.94) 1(18180.74,12994.4) 1(18180.74,12998.52) 1(18180.74,13002.64) 1(18180.74,13006.76) 1(18180.74,13010.88) 1(18180.74,13015) 1(18180.74,13019.12) 1(18180.74,13023.24) 1(18180.74,13027.36) 1(18180.74,13031.48) 1(18180.74,13035.6) 1(18180.74,13039.72) 1(18180.74,13043.84) 1(18180.74,13047.96) 1(18180.74,13052.08) 1(18180.74,13056.2) 1(18180.74,13060.32) 1(18180.74,13064.44) 1(18180.74,13068.56) 1(18180.74,13072.68) 1(18180.74,13076.8) 1(18180.74,13944.4) 1(18180.74,13948.52) 1(18180.74,13952.64) 1(18180.74,13956.76) 1(18180.74,13960.88) 1(18180.74,13965) 1(18180.74,13969.12) 1(18180.74,13973.24) 1(18180.74,13977.36) 1(18180.74,13981.48) 1(18180.74,13985.6) 1(18180.74,13989.72) 1(18180.74,13993.84) 1(18180.74,13997.96) 1(18180.74,14002.08) 1(18180.74,14006.2) 1(18180.74,14010.32) 1(18180.74,14014.44) 1(18180.74,14018.56) 1(18180.74,14022.68) 1(18180.74,14026.8) 1(18186.02,8868.02) 1(18270.49,13442.54) 1(18270.49,13446.66) 1(18270.49,13450.78) 1(18270.49,13454.9) 1(18270.49,13459.02) 1(18270.49,13463.14) 1(18270.49,13467.26) 1(18270.49,13471.38) 1(18270.49,13475.5) 1(18270.49,13479.62) 1(18270.49,13483.74) 1(18270.49,13487.86) 1(18270.49,13491.98) 1(18270.49,13496.1) 1(18270.49,13500.22) 1(18270.49,13504.34) 1(18270.49,13508.46) 1(18270.49,13512.58) 1(18270.49,13516.7) 1(18270.49,13520.82) 1(18270.49,13524.94) 1(18270.5,12994.4) 1(18270.5,12998.52) 1(18270.5,13002.64) 1(18270.5,13006.76) 1(18270.5,13010.88) 1(18270.5,13015) 1(18270.5,13019.12) 1(18270.5,13023.24) 1(18270.5,13027.36) 1(18270.5,13031.48) 1(18270.5,13035.6) 1(18270.5,13039.72) 1(18270.5,13043.84) 1(18270.5,13047.96) 1(18270.5,13052.08) 1(18270.5,13056.2) 1(18270.5,13060.32) 1(18270.5,13064.44) 1(18270.5,13068.56) 1(18270.5,13072.68) 1(18270.5,13076.8) 1(18270.5,13944.4) 1(18270.5,13948.52) 1(18270.5,13952.64) 1(18270.5,13956.76) 1(18270.5,13960.88) 1(18270.5,13965) 1(18270.5,13969.12) 1(18270.5,13973.24) 1(18270.5,13977.36) 1(18270.5,13981.48) 1(18270.5,13985.6) 1(18270.5,13989.72) 1(18270.5,13993.84) 1(18270.5,13997.96) 1(18270.5,14002.08) 1(18270.5,14006.2) 1(18270.5,14010.32) 1(18270.5,14014.44) 1(18270.5,14018.56) 1(18270.5,14022.68) 1(18270.5,14026.8) 1(18272.38,14536.55) 1(18272.38,14536.55) 1(18272.38,14636.55) 1(18272.38,14636.55) 1(18274.83,13432.52) 1(18274.83,13432.52) 1(18274.83,13532.52) 1(18274.83,13532.52) 1(18275.62,12985.16) 1(18275.62,12985.16) 1(18275.62,12985.16) 1(18275.62,12985.16) 1(18275.62,13085.16) 1(18275.62,13085.16) 1(18275.62,13085.16) 1(18275.62,13085.16) 1(18275.62,13135.16) 1(18275.62,13135.16) 1(18275.62,13235.16) 1(18275.62,13235.16) 1(18275.62,13285.16) 1(18275.62,13285.16) 1(18275.62,13385.16) 1(18275.62,13385.16) 1(18275.62,13435.16) 1(18275.62,13435.16) 1(18275.62,13435.16) 1(18275.62,13435.16) 1(18275.62,13535.16) 1(18275.62,13535.16) 1(18275.62,13535.16) 1(18275.62,13535.16) 1(18275.62,13585.16) 1(18275.62,13585.16) 1(18275.62,13585.16) 1(18275.62,13585.16) 1(18275.62,13685.16) 1(18275.62,13685.16) 1(18275.62,13685.16) 1(18275.62,13685.16) 1(18275.62,13935.16) 1(18275.62,13935.16) 1(18275.62,13935.16) 1(18275.62,13935.16) 1(18275.62,14035.16) 1(18275.62,14035.16) 1(18275.62,14035.16) 1(18275.62,14035.16) 1(18275.62,14085.16) 1(18275.62,14085.16) 1(18275.62,14085.16) 1(18275.62,14085.16) 1(18275.62,14185.16) 1(18275.62,14185.16) 1(18275.62,14185.16) 1(18275.62,14185.16) 1(18275.62,14235.16) 1(18275.62,14235.16) 1(18275.62,14335.16) 1(18275.62,14335.16) 1(18275.62,14385.16) 1(18275.62,14385.16) 1(18275.62,14485.16) 1(18275.62,14485.16) 1(18750.82,14710.36) 1(18750.82,14860.36) 1(18786.02,8538.49) 1(18786.02,8868.02) 1(18786.02,8868.02) 1(18786.18,9079.52) 1(18786.18,9518.89) 1(18786.18,9518.89) 1(18786.18,9518.89) 1(18850.4,14235.16) 1(18850.4,14235.16) 1(18850.4,14335.16) 1(18850.4,14335.16) 1(18850.4,14385.16) 1(18850.4,14385.16) 1(18850.4,14485.16) 1(18850.4,14485.16) 1(18850.4,14535.16) 1(18850.4,14535.16) 1(18850.4,14635.16) 1(18850.4,14635.16) 1(18850.82,13135.16) 1(18850.82,13135.16) 1(18850.82,13235.16) 1(18850.82,13235.16) 1(18850.82,13285.16) 1(18850.82,13285.16) 1(18850.82,13285.16) 1(18850.82,13285.16) 1(18850.82,13385.16) 1(18850.82,13385.16) 1(18850.82,13385.16) 1(18850.82,13385.16) 1(18850.82,13435.16) 1(18850.82,13435.16) 1(18850.82,13535.16) 1(18850.82,13535.16) 1(18850.82,13585.16) 1(18850.82,13585.16) 1(18850.82,13685.16) 1(18850.82,13685.16) 1(18850.82,13935.16) 1(18850.82,13935.16) 1(18850.82,14035.16) 1(18850.82,14035.16) 1(18850.82,14085.16) 1(18850.82,14085.16) 1(18850.82,14185.16) 1(18850.82,14185.16) 1(18855.94,13294.4) 1(18855.94,13298.52) 1(18855.94,13302.64) 1(18855.94,13306.76) 1(18855.94,13310.88) 1(18855.94,13315) 1(18855.94,13319.12) 1(18855.94,13323.24) 1(18855.94,13327.36) 1(18855.94,13331.48) 1(18855.94,13335.6) 1(18855.94,13339.72) 1(18855.94,13343.84) 1(18855.94,13347.96) 1(18855.94,13352.08) 1(18855.94,13356.2) 1(18855.94,13360.32) 1(18855.94,13364.44) 1(18855.94,13368.56) 1(18855.94,13372.68) 1(18855.94,13376.8) 1(18856.72,14095.18) 1(18856.72,14099.3) 1(18856.72,14103.42) 1(18856.72,14107.54) 1(18856.72,14111.66) 1(18856.72,14115.78) 1(18856.72,14119.9) 1(18856.72,14124.02) 1(18856.72,14128.14) 1(18856.72,14132.26) 1(18856.72,14136.38) 1(18856.72,14140.5) 1(18856.72,14144.62) 1(18856.72,14148.74) 1(18856.72,14152.86) 1(18856.72,14156.98) 1(18856.72,14161.1) 1(18856.72,14165.22) 1(18856.72,14169.34) 1(18856.72,14173.46) 1(18856.72,14177.58) 1(18945.71,13294.4) 1(18945.71,13298.52) 1(18945.71,13302.64) 1(18945.71,13306.76) 1(18945.71,13310.88) 1(18945.71,13315) 1(18945.71,13319.12) 1(18945.71,13323.24) 1(18945.71,13327.36) 1(18945.71,13331.48) 1(18945.71,13335.6) 1(18945.71,13339.72) 1(18945.71,13343.84) 1(18945.71,13347.96) 1(18945.71,13352.08) 1(18945.71,13356.2) 1(18945.71,13360.32) 1(18945.71,13364.44) 1(18945.71,13368.56) 1(18945.71,13372.68) 1(18945.71,13376.8) 1(18946.49,14095.18) 1(18946.49,14099.3) 1(18946.49,14103.42) 1(18946.49,14107.54) 1(18946.49,14111.66) 1(18946.49,14115.78) 1(18946.49,14119.9) 1(18946.49,14124.02) 1(18946.49,14128.14) 1(18946.49,14132.26) 1(18946.49,14136.38) 1(18946.49,14140.5) 1(18946.49,14144.62) 1(18946.49,14148.74) 1(18946.49,14152.86) 1(18946.49,14156.98) 1(18946.49,14161.1) 1(18946.49,14165.22) 1(18946.49,14169.34) 1(18946.49,14173.46) 1(18946.49,14177.58) 1(18950.4,14235.16) 1(18950.4,14235.16) 1(18950.4,14335.16) 1(18950.4,14335.16) 1(18950.4,14385.16) 1(18950.4,14385.16) 1(18950.4,14485.16) 1(18950.4,14485.16) 1(18950.4,14535.16) 1(18950.4,14535.16) 1(18950.4,14635.16) 1(18950.4,14635.16) 1(18950.83,13135.16) 1(18950.83,13135.16) 1(18950.83,13235.16) 1(18950.83,13235.16) 1(18950.83,13285.16) 1(18950.83,13285.16) 1(18950.83,13285.16) 1(18950.83,13285.16) 1(18950.83,13385.16) 1(18950.83,13385.16) 1(18950.83,13385.16) 1(18950.83,13385.16) 1(18950.83,13435.16) 1(18950.83,13435.16) 1(18950.83,13535.16) 1(18950.83,13535.16) 1(18950.83,13585.16) 1(18950.83,13585.16) 1(18950.83,13685.16) 1(18950.83,13685.16) 1(18950.83,13935.16) 1(18950.83,13935.16) 1(18950.83,14035.16) 1(18950.83,14035.16) 1(18950.83,14085.16) 1(18950.83,14085.16) 1(18950.83,14185.16) 1(18950.83,14185.16) 1(19425.63,13709.17) 1(19425.63,13860.75) 1(19475.63,13935.16) 1(19475.63,13935.16) 1(19475.63,14035.16) 1(19475.63,14035.16) 1(19475.63,14085.16) 1(19475.63,14085.16) 1(19475.63,14185.16) 1(19475.63,14185.16) 1(19476.38,14235.55) 1(19476.38,14235.55) 1(19476.38,14335.55) 1(19476.38,14335.55) 1(19476.38,14385.55) 1(19476.38,14385.55) 1(19476.38,14485.55) 1(19476.38,14485.55) 1(19476.38,14535.55) 1(19476.38,14535.55) 1(19476.38,14535.55) 1(19476.38,14535.55) 1(19476.38,14635.55) 1(19476.38,14635.55) 1(19476.38,14635.55) 1(19476.38,14635.55) 1(19477.62,14536.52) 1(19477.62,14536.52) 1(19477.62,14636.52) 1(19477.62,14636.52) 1(19483.52,14546.54) 1(19483.52,14550.66) 1(19483.52,14554.78) 1(19483.52,14558.9) 1(19483.52,14563.02) 1(19483.52,14567.14) 1(19483.52,14571.26) 1(19483.52,14575.38) 1(19483.52,14579.5) 1(19483.52,14583.62) 1(19483.52,14587.74) 1(19483.52,14591.86) 1(19483.52,14595.98) 1(19483.52,14600.1) 1(19483.52,14604.22) 1(19483.52,14608.34) 1(19483.52,14612.46) 1(19483.52,14616.58) 1(19483.52,14620.7) 1(19483.52,14624.82) 1(19483.52,14628.94) 1(19486.02,8538.49) 1(19486.02,8868.02) 1(19486.02,8868.02) 1(19486.02,8868.02) 1(19486.18,9079.52) 1(19486.18,9368.89) 1(19486.18,9518.89) 1(19486.18,9518.89) 1(19486.18,9518.89) 1(19573.28,14546.54) 1(19573.28,14550.66) 1(19573.28,14554.78) 1(19573.28,14558.9) 1(19573.28,14563.02) 1(19573.28,14567.14) 1(19573.28,14571.26) 1(19573.28,14575.38) 1(19573.28,14579.5) 1(19573.28,14583.62) 1(19573.28,14587.74) 1(19573.28,14591.86) 1(19573.28,14595.98) 1(19573.28,14600.1) 1(19573.28,14604.22) 1(19573.28,14608.34) 1(19573.28,14612.46) 1(19573.28,14616.58) 1(19573.28,14620.7) 1(19573.28,14624.82) 1(19573.28,14628.94) 1(19575.63,13935.16) 1(19575.63,13935.16) 1(19575.63,14035.16) 1(19575.63,14035.16) 1(19575.63,14085.16) 1(19575.63,14085.16) 1(19575.63,14185.16) 1(19575.63,14185.16) 1(19576.38,14235.55) 1(19576.38,14235.55) 1(19576.38,14335.55) 1(19576.38,14335.55) 1(19576.38,14385.55) 1(19576.38,14385.55) 1(19576.38,14485.55) 1(19576.38,14485.55) 1(19576.38,14535.55) 1(19576.38,14535.55) 1(19576.38,14535.55) 1(19576.38,14535.55) 1(19576.38,14635.55) 1(19576.38,14635.55) 1(19576.38,14635.55) 1(19576.38,14635.55) 1(19577.62,14536.52) 1(19577.62,14536.52) 1(19577.62,14636.52) 1(19577.62,14636.52) 1(19612.94,14710.36) 1(19612.94,14860.06) 1(19848.83,13435.16) 1(19848.83,13435.16) 1(19848.83,13535.16) 1(19848.83,13535.16) 1(19850.83,13135.16) 1(19850.83,13135.16) 1(19850.83,13235.16) 1(19850.83,13235.16) 1(19850.83,13585.16) 1(19850.83,13585.16) 1(19850.83,13685.16) 1(19850.83,13685.16) 1(19948.83,13435.16) 1(19948.83,13435.16) 1(19948.83,13535.16) 1(19948.83,13535.16) 1(19950.83,13135.16) 1(19950.83,13135.16) 1(19950.83,13235.16) 1(19950.83,13235.16) 1(19950.83,13585.16) 1(19950.83,13585.16) 1(19950.83,13685.16) 1(19950.83,13685.16) 1(19975.63,13709.96) 1(19975.63,13860.36) 1(20086.02,8538.49) 1(20086.02,8868.02) 1(20086.02,8868.02) 1(20086.02,8868.02) 1(20086.18,9079.52) 1(20086.18,9368.89) 1(20086.18,9518.89) 1(20086.18,9518.89) 1(20086.18,9518.89) 1(20125.63,14710.36) 1(20125.63,14860.36) 1(20250,13935.16) 1(20250,13935.16) 1(20250,14035.16) 1(20250,14035.16) 1(20250,14085.16) 1(20250,14085.16) 1(20250,14185.16) 1(20250,14185.16) 1(20250,14235.16) 1(20250,14235.16) 1(20250,14335.16) 1(20250,14335.16) 1(20250.4,14385.16) 1(20250.4,14385.16) 1(20250.4,14485.16) 1(20250.4,14485.16) 1(20250.4,14535.16) 1(20250.4,14535.16) 1(20250.4,14635.16) 1(20250.4,14635.16) 1(20350,13935.16) 1(20350,13935.16) 1(20350,14035.16) 1(20350,14035.16) 1(20350,14085.16) 1(20350,14085.16) 1(20350,14185.16) 1(20350,14185.16) 1(20350,14235.16) 1(20350,14235.16) 1(20350,14335.16) 1(20350,14335.16) 1(20350.4,14385.16) 1(20350.4,14385.16) 1(20350.4,14485.16) 1(20350.4,14485.16) 1(20350.4,14535.16) 1(20350.4,14535.16) 1(20350.4,14635.16) 1(20350.4,14635.16) 1(20577.13,14710.36) 1(20577.13,14860.36) 1(20825.63,12985.16) 1(20825.63,12985.16) 1(20825.63,13085.16) 1(20825.63,13085.16) 1(20825.63,13135.16) 1(20825.63,13135.16) 1(20825.63,13135.16) 1(20825.63,13135.16) 1(20825.63,13235.16) 1(20825.63,13235.16) 1(20825.63,13235.16) 1(20825.63,13235.16) 1(20825.63,13435.16) 1(20825.63,13435.16) 1(20825.63,13535.16) 1(20825.63,13535.16) 1(20825.63,13585.16) 1(20825.63,13585.16) 1(20825.63,13685.16) 1(20825.63,13685.16) 1(20830.75,13144.4) 1(20830.75,13148.52) 1(20830.75,13152.64) 1(20830.75,13156.76) 1(20830.75,13160.88) 1(20830.75,13165) 1(20830.75,13169.12) 1(20830.75,13173.24) 1(20830.75,13177.36) 1(20830.75,13181.48) 1(20830.75,13185.6) 1(20830.75,13189.72) 1(20830.75,13193.84) 1(20830.75,13197.96) 1(20830.75,13202.08) 1(20830.75,13206.2) 1(20830.75,13210.32) 1(20830.75,13214.44) 1(20830.75,13218.56) 1(20830.75,13222.68) 1(20830.75,13226.8) 1(20836.02,8538.49) 1(20836.02,8868.02) 1(20836.02,8868.02) 1(20836.02,8868.02) 1(20836.18,9079.52) 1(20836.18,9518.89) 1(20836.18,9518.89) 1(20836.18,9518.89) 1(20920.51,13144.4) 1(20920.51,13148.52) 1(20920.51,13152.64) 1(20920.51,13156.76) 1(20920.51,13160.88) 1(20920.51,13165) 1(20920.51,13169.12) 1(20920.51,13173.24) 1(20920.51,13177.36) 1(20920.51,13181.48) 1(20920.51,13185.6) 1(20920.51,13189.72) 1(20920.51,13193.84) 1(20920.51,13197.96) 1(20920.51,13202.08) 1(20920.51,13206.2) 1(20920.51,13210.32) 1(20920.51,13214.44) 1(20920.51,13218.56) 1(20920.51,13222.68) 1(20920.51,13226.8) 1(20925.63,12985.16) 1(20925.63,12985.16) 1(20925.63,13085.16) 1(20925.63,13085.16) 1(20925.63,13135.16) 1(20925.63,13135.16) 1(20925.63,13135.16) 1(20925.63,13135.16) 1(20925.63,13235.16) 1(20925.63,13235.16) 1(20925.63,13235.16) 1(20925.63,13235.16) 1(20925.63,13435.16) 1(20925.63,13435.16) 1(20925.63,13535.16) 1(20925.63,13535.16) 1(20925.63,13585.16) 1(20925.63,13585.16) 1(20925.63,13685.16) 1(20925.63,13685.16) 1(20937.44,14232.01) 1(20937.44,14232.01) 1(20937.44,14332.01) 1(20937.44,14332.01) 1(20937.44,14532.01) 1(20937.44,14532.01) 1(20937.44,14632.01) 1(20937.44,14632.01) 1(21037.44,14232.01) 1(21037.44,14232.01) 1(21037.44,14332.01) 1(21037.44,14332.01) 1(21037.44,14532.01) 1(21037.44,14532.01) 1(21037.44,14632.01) 1(21037.44,14632.01) 1(21286.02,8538.49) 1(21286.02,8648.33) 1(21286.02,8758.18) 1(21286.02,8868.02) 1(21286.02,8868.02) 1(21310.82,8537.02) 1(21310.82,8538.49) 1(21310.82,8648.33) 1(21310.82,8758.18) 1(21310.82,8868.02) 1(21310.82,8868.02) 1(21310.82,8868.02) 1(21310.99,9079.52) 1(21310.99,9079.52) 1(21310.99,9189.36) 1(21310.99,9299.2) 1(21310.99,9409.05) 1(21310.99,9518.89) 1(21310.99,9518.89) 1(21310.99,9518.89) 1(21523.63,9762.51) 1(21524.63,9738.97) 1(21525.63,8308.02) 1(21525.63,8308.02) 1(21525.63,11284.8) 1(21525.63,11338.3) 1(21525.63,12656.02) 1(21525.63,12803.26) 1(21525.63,12957.21) 1(21525.63,12959.96) 1(21525.63,12959.96) 1(21525.63,13109.96) 1(21525.63,13259.96) 1(21525.63,13409.96) 1(21525.63,13559.96) 1(21525.63,13709.96) 1(21525.63,13860.36) 1(21525.63,13910.36) 1(21525.63,14060.36) 1(21525.63,14210.36) 1(21525.63,14360.36) 1(21525.63,14510.36) 1(21525.63,14660.36) 1(21525.63,14710.36) 1(21525.63,14860.36) 1(21525.63,14860.36)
